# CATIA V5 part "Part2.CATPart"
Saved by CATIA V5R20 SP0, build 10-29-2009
Part number: Bâti
Bounding box of the stored display mesh (mm): x -45 to 45, y -20 to 920, z -500 to 20
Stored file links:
  D:\Dropbox\IAO_2011\MMS_GR1\0\video\IAO_2011_1503_rjugie\rjugie\IAO_2011_1503_rjugie\Part2.CATPart
  D:\Dropbox\IAO_2011\MMS_GR1\0\video\IAO_2011_1503_rjugie\rjugie\IAO_2011_1503_rjugie\rjugie.CATProduct
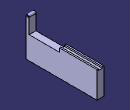
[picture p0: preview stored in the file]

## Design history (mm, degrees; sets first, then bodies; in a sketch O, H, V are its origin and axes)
External parameters (linked from other documents)
  `External.Rayon_extérieur_bielle` = 20 mm
  External.he = 400 mm
  External.Rayon_trou_bielle = 10 mm
Set1
  Plane1: linked copy from another document
  Point1 "A": linked copy from another document
Body1 (main body)
  Sketch1 on Plane1, origin (0, 0, 0), H (0, 1, 0), V (0, 0, 1)
    line L1 (-20, 0) -> (-20, -500)
    point P1 (-20, 0)
    line L2 (20, 0) -> (20, -200)
    point P3 (20, 0)
    reference projected point E1 (0, 0) from Point1
    reference projected point E2 (0, 0) from Point1
    arc A1 centre (0, 0) radius 20 from (-20, 0) to (20, 0) cw
    line L3 (20, -200) -> (420, -200)
    line L4 (420, -200) -> (420, -150)
    line L5 (420, -150) -> (920, -150)
    line L6 (920, -150) -> (920, -500)
    line L7 (920, -500) -> (-20, -500)
    circle A2 centre (0, 0) radius 10
    point P10 (0, 0)
    reference projected point E3 (0, 0) from Point1
    distance L2 E1 = 20 {= `External.Rayon_extérieur_bielle`}
    distance E2 L1 = 20 {= `External.Rayon_extérieur_bielle`}
    length L2 = 200
    length L1 = 500
    length L3 = 400 {= External.he}
    length L5 = 500
    radius A2 = 10 {= External.Rayon_trou_bielle}
    length L4 = 50
    coincidence: P1 H, P3 H, E3 P10
    vertical: L1 V, L2 V, L4 V, L6 V
    tangency: A1 L1
    horizontal: L3 H, L5 H, L7 H
  Pad1: profile Sketch1, direction (1, 0, 0), length 45, opposite side length 45
  Sketch2 on face of Pad1 from Sketch1.L5, origin (0, 0, -150), H (1, 0, 0), V (0, 1, 0)
    line L1 (-25, 920) -> (25, 920)
    line L2 (25, 920) -> (25, 420)
    line L3 (25, 420) -> (-25, 420)
    line L4 (-25, 420) -> (-25, 920)
    reference projected line E1 (-45, 420) -> (45, 420) from edge [face of Pad1 from Sketch1.L4 | face of Pad1 from Sketch1.L5]
    reference projected line E2 (-45, 920) -> (45, 920) from edge [face of Pad1 from Sketch1.L5 | face of Pad1 from Sketch1.L6]
    reference projected line E3 (45, 920) -> (45, 420) from edge [face of Pad1 from Sketch1.L5 | end face of Pad1]
    reference projected line E4 (-45, 920) -> (-45, 420) from edge [start face of Pad1 | face of Pad1 from Sketch1.L5]
    distance L2 E3 = 20
    distance L4 E4 = 20
    horizontal: L1 H, L3 H
    vertical: L2 V, L4 V
    coincidence: L3 E1, L1 E2
  Pocket1: profile Sketch2, direction (0, 0, -1), length 20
